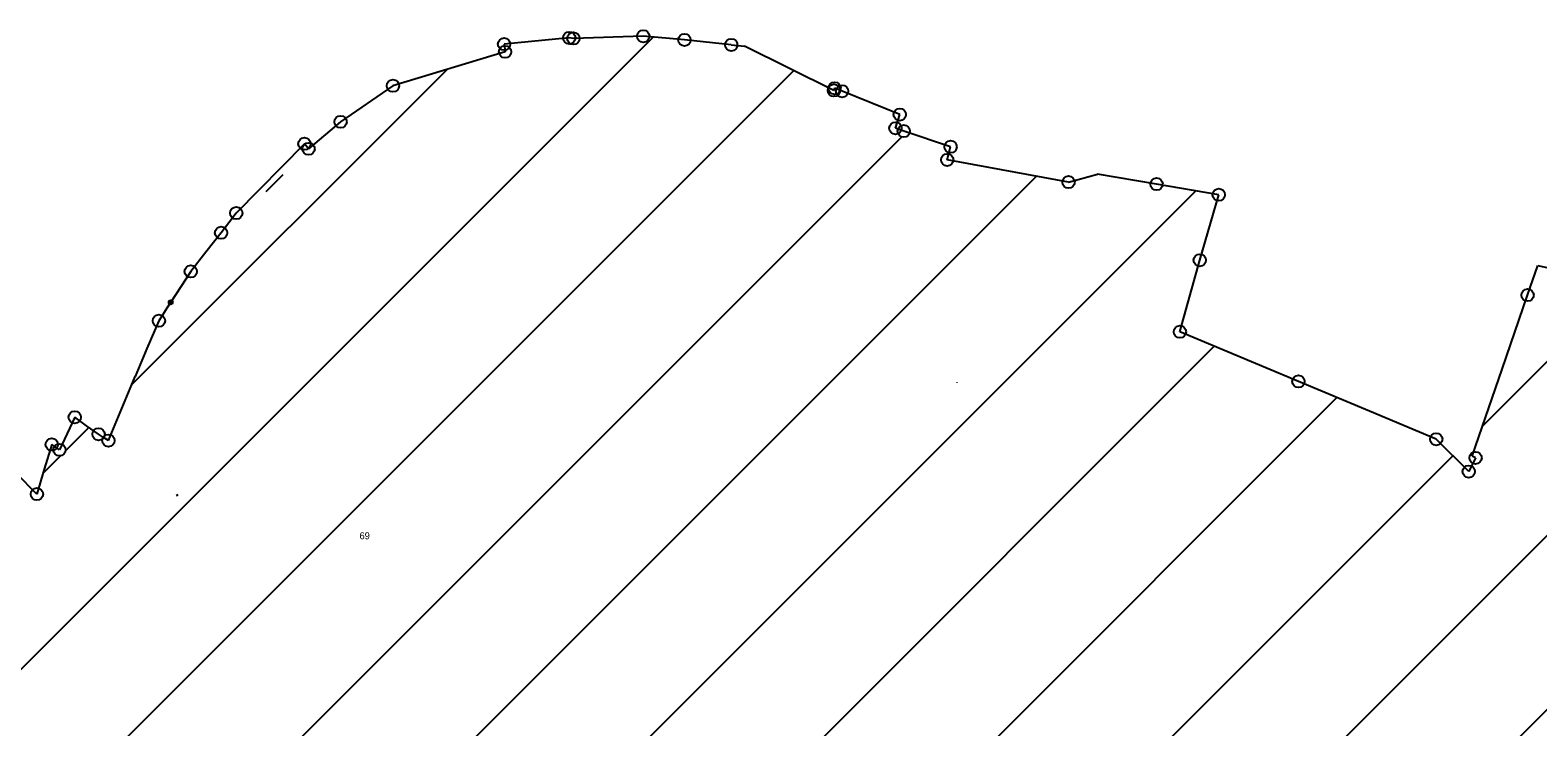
# Model space of a CAD drawing. Extents: x -623137 to -616791, y -1192758 to -1186540.
# Drawn here: x -618627.9 to -618260.3, y -1189187.2 to -1189017.3 of the extents above; entities that cross this region are included whole.
import ezdxf

# ---------------------------------------------------------------- set-up
doc = ezdxf.new("R2010")
doc.units = 0
for name, color, linetype in [('Hranice parcel', 7, 'Continuous'), ('Legenda', 7, 'Continuous'), ('Parcelní čísla', 7, 'Continuous'), ('Pop_ PČ_ popisy', 7, 'Continuous'), ('Vnitřní kresba', 7, 'Continuous'), ('Vrstva 13', 7, 'Continuous'), ('Vzdy červené', 7, 'Continuous'), ('Značky bodu BP', 7, 'Continuous')]:
    doc.layers.add(name, color=color, linetype=linetype)

msp = doc.modelspace()

# ---------------------------------------------------------------- linework, layer by layer
at = {"layer": 'Hranice parcel'}
for points in [[(-618277.16, -1189124.93), (-618285.07, -1189117.05)], [(-618275.48, -1189121.6), (-618276.29, -1189121.19)], [(-618275.48, -1189121.6), (-618277.16, -1189124.93)]]:
    msp.add_lwpolyline(points, dxfattribs=at)
at = {"layer": 'Legenda'}
for p, q in [((-618796.59, -1189339.66), (-618475.94, -1189019.02)), ((-618768.66, -1189354.16), (-618441.66, -1189027.16)), ((-618603.08, -1189103.73), (-618526.22, -1189026.86)), ((-618726.58, -1189354.51), (-618415.39, -1189043.32)), ((-618684.77, -1189355.12), (-618382.56, -1189052.92)), ((-618641.76, -1189354.54), (-618343.69, -1189056.47)), ((-618273.77, -1189113.83), (-618235.77, -1189075.83)), ((-618549.52, -1189432), (-618201.17, -1189083.65)), ((-618638.82, -1189394.02), (-618339.17, -1189094.37)), ((-618466.46, -1189391.37), (-618167.33, -1189092.25)), ((-618600.9, -1189398.53), (-618309.27, -1189106.9)), ((-618619.23, -1189119.88), (-618613.69, -1189114.34)), ((-618624.71, -1189125.35), (-618620.47, -1189121.12)), ((-618573.01, -1189413.07), (-618281.02, -1189121.08))]:
    msp.add_line(p, q, dxfattribs=at)
at = {"layer": 'Pop_ PČ_ popisy'}
for points in [[(-618401.89, -1189103.3), (-618401.84, -1189103.24)], [(-618591.89, -1189130.64), (-618592.22, -1189130.86)]]:
    msp.add_lwpolyline(points, dxfattribs=at)
at = {"layer": 'Vnitřní kresba'}
msp.add_lwpolyline([(-618566.26, -1189052.61), (-618570.38, -1189056.72)], dxfattribs=at)
at = {"layer": 'Vrstva 13'}
for p, q in [((-618496.44, -1189019.2), (-618512.32, -1189020.7)), ((-618512.32, -1189020.7), (-618512.08, -1189022.59)), ((-618495.43, -1189019.3), (-618496.44, -1189019.2)), ((-618478.38, -1189018.8), (-618495.43, -1189019.3)), ((-618468.34, -1189019.7), (-618478.38, -1189018.8)), ((-618456.92, -1189020.89), (-618468.34, -1189019.7)), ((-618456.92, -1189020.89), (-618456.92, -1189020.89)), ((-618456.92, -1189020.89), (-618453.68, -1189021.23)), ((-618431.89, -1189031.98), (-618453.68, -1189021.23)), ((-618512.08, -1189022.59), (-618539.4, -1189030.85)), ((-618539.4, -1189030.85), (-618552.17, -1189039.66)), ((-618431.74, -1189031.46), (-618431.89, -1189031.98)), ((-618431.89, -1189031.98), (-618431.89, -1189031.98)), ((-618429.91, -1189032.2), (-618431.74, -1189031.46)), ((-618415.86, -1189037.89), (-618429.91, -1189032.2)), ((-618552.17, -1189039.66), (-618559.97, -1189046.24)), ((-618416.92, -1189041.23), (-618415.86, -1189037.89)), ((-618414.88, -1189041.91), (-618416.92, -1189041.23)), ((-618403.45, -1189045.73), (-618414.88, -1189041.91)), ((-618561, -1189045.01), (-618577.6, -1189061.89)), ((-618559.97, -1189046.24), (-618561, -1189045.01)), ((-618404.28, -1189048.93), (-618403.45, -1189045.73)), ((-618374.71, -1189054.36), (-618404.28, -1189048.93)), ((-618374.71, -1189054.36), (-618367.61, -1189052.39)), ((-618374.71, -1189054.36), (-618374.71, -1189054.36)), ((-618353.24, -1189054.84), (-618367.61, -1189052.39)), ((-618338.08, -1189057.42), (-618353.24, -1189054.84)), ((-618342.71, -1189073.41), (-618338.08, -1189057.42)), ((-618577.6, -1189061.89), (-618579.45, -1189064.3)), ((-618579.45, -1189064.3), (-618581.3, -1189066.71)), ((-618581.3, -1189066.71), (-618585.01, -1189071.43)), ((-618581.3, -1189066.71), (-618581.3, -1189066.71)), ((-618585.01, -1189071.43), (-618588.71, -1189076.14)), ((-618347.55, -1189090.86), (-618342.71, -1189073.41)), ((-618588.71, -1189076.14), (-618591.15, -1189079.91)), ((-618262.79, -1189081.91), (-618260.3, -1189074.69)), ((-618260.3, -1189074.69), (-618248.18, -1189077.38)), ((-618591.15, -1189079.91), (-618593.58, -1189083.67)), ((-618595.03, -1189085.91), (-618593.58, -1189083.67)), ((-618269.03, -1189099.96), (-618262.79, -1189081.91)), ((-618596.48, -1189088.15), (-618599.37, -1189094.96)), ((-618595.03, -1189085.91), (-618596.48, -1189088.15)), ((-618318.66, -1189102.97), (-618347.55, -1189090.86)), ((-618599.37, -1189094.96), (-618602.26, -1189101.77)), ((-618608.79, -1189117.39), (-618602.26, -1189101.77)), ((-618276.29, -1189121.19), (-618269.03, -1189099.96)), ((-618318.66, -1189102.97), (-618318.66, -1189102.97)), ((-618301.33, -1189110.23), (-618318.66, -1189102.97)), ((-618285.07, -1189117.05), (-618301.33, -1189110.23)), ((-618626.22, -1189130.42), (-618643.17, -1189113.36)), ((-618616.99, -1189111.71), (-618618.85, -1189115.68)), ((-618614.08, -1189113.77), (-618616.99, -1189111.71)), ((-618611.17, -1189115.83), (-618614.08, -1189113.77)), ((-618618.85, -1189115.68), (-618620.71, -1189119.64)), ((-618618.85, -1189115.68), (-618618.85, -1189115.68)), ((-618609.98, -1189116.61), (-618611.17, -1189115.83)), ((-618608.79, -1189117.39), (-618609.98, -1189116.61)), ((-618277.16, -1189124.93), (-618285.07, -1189117.05)), ((-618622.6, -1189118.31), (-618624.41, -1189124.36)), ((-618621.65, -1189118.98), (-618622.6, -1189118.31)), ((-618620.71, -1189119.64), (-618621.65, -1189118.98)), ((-618275.48, -1189121.6), (-618276.29, -1189121.19)), ((-618624.41, -1189124.36), (-618626.22, -1189130.42)), ((-618275.48, -1189121.6), (-618277.16, -1189124.93)), ((-618277.16, -1189124.93), (-618277.16, -1189124.93)), ((-618277.16, -1189124.93), (-618277.16, -1189124.93)), ((-618626.22, -1189130.42), (-618626.22, -1189130.42)), ((-618626.22, -1189130.42), (-618626.22, -1189130.42))]:
    msp.add_line(p, q, dxfattribs=at)
at = {"layer": 'Vzdy červené'}
for centre in [(-618496.44, -1189019.2), (-618495.43, -1189019.3), (-618478.38, -1189018.8), (-618468.34, -1189019.7), (-618512.32, -1189020.7), (-618512.08, -1189022.59), (-618456.92, -1189020.89), (-618539.4, -1189030.85), (-618431.89, -1189031.98), (-618431.74, -1189031.46), (-618429.91, -1189032.2), (-618415.86, -1189037.89), (-618552.17, -1189039.66), (-618416.92, -1189041.23), (-618414.88, -1189041.91), (-618561, -1189045.01), (-618559.97, -1189046.24), (-618404.28, -1189048.93), (-618403.45, -1189045.73), (-618374.71, -1189054.36), (-618353.24, -1189054.84), (-618338.08, -1189057.42), (-618577.6, -1189061.89), (-618581.3, -1189066.71), (-618342.71, -1189073.41), (-618588.71, -1189076.14), (-618262.79, -1189081.91), (-618596.48, -1189088.15), (-618347.55, -1189090.86), (-618318.66, -1189102.97), (-618616.99, -1189111.71), (-618622.6, -1189118.31), (-618611.17, -1189115.83), (-618608.79, -1189117.39), (-618285.07, -1189117.05), (-618620.71, -1189119.64), (-618275.48, -1189121.6), (-618277.16, -1189124.93), (-618626.22, -1189130.42)]:
    msp.add_circle(centre, 1.5, dxfattribs=at)
at = {"layer": 'Značky bodu BP'}
for radius in [0.5, 0.0303]:
    msp.add_circle((-618593.58, -1189083.67), radius, dxfattribs=at)

# ---------------------------------------------------------------- texts
at = {"layer": 'Parcelní čísla'}
for s, height, p in [('2007/20', 0.1, (-618592.15, -1189130.64)), ('69', 1.7, (-618547.57, -1189141.45))]:
    msp.add_text(s, height=height, dxfattribs=at).set_placement(p)

doc.saveas('drawing.dxf')
